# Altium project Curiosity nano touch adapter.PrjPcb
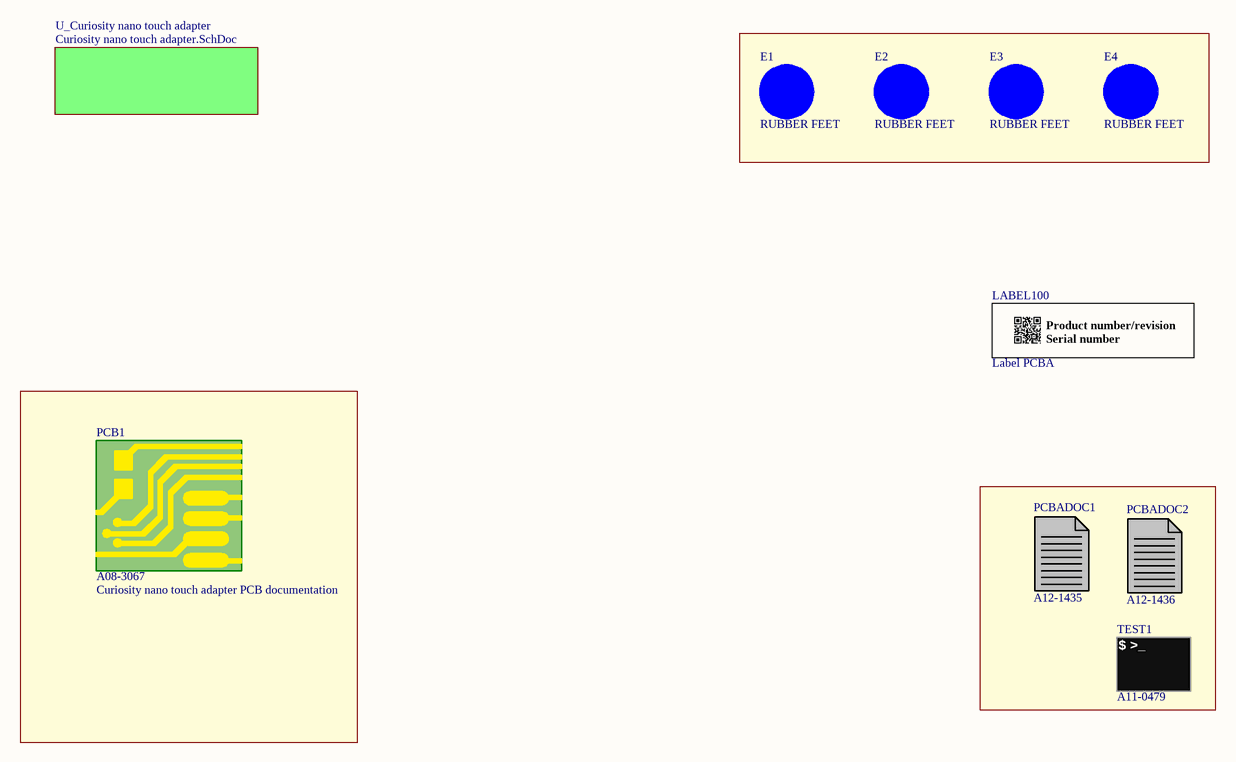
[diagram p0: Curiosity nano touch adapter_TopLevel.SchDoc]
ProjectTitle: Curiosity nano touch adapter Kit; ProjectRevisionSCH: 1; ProjectRevisionFAB: 1; ProjectRevisionASSY: 1; ProjectRevisionART: 1; ProjectPartNumber: **; ProjectEngineer: Sivaram.SL; ProjectDrawnBy: Sivaram.SL; ProjectBoardNumber: **; PCBNumber_TLM: A12-1436; PCBANumber_TLM: A09-3346
2 sheets, 27 parts. Net scope: global (net labels, ports and power ports of the same name join across sheets).
Board file: Curiosity nano touch adapter.PcbDoc
Sheets:
  Curiosity nano touch adapter_TopLevel.SchDoc
    U_Curiosity nano touch adapter = Curiosity nano touch adapter.SchDoc

## Sheet Curiosity nano touch adapter_TopLevel.SchDoc: Top Level
size A3; Organization: ATMEL Norway; Address1: Vestre Rosten 79; Address2: N-7075 TILLER; Address3: NORWAY; DocumentNumber: 1; Revision: 3; SheetNumber: 1; SheetTotal: 2; PageSetup: Record=PageOptions¦CenterHorizontal=True¦CenterVertical=True¦PrintScale=1.01¦XCorrection=1.00¦YCorrection=1.00¦PrintKind=1¦BorderSize=5000000¦LeftOffset=0¦BottomOffset=0¦Orientation=2¦PaperLength=1000¦PaperWidth=1000¦Scale=100¦PaperSource=7¦PrintQuality=-4¦MediaType=1¦DitherType=10¦PaperKind=Letter¦PrintScaleMode=1

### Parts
?  (no value)  (graphical)
E1  RUBBER FEET  [AP8-00192]
E2  RUBBER FEET  [AP8-00192]
E3  RUBBER FEET  [AP8-00192]
E4  RUBBER FEET  [AP8-00192]
LABEL100  value Label PCBA  [AP8-00317]
PCB1  value Curiosity nano touch adapter PCB documentation  AN: A08-3067  (hidden comment: PCB)  (mechanical)
PCBADOC1  AN: A12-1435  (hidden comment: PCBADOC)  (mechanical)
PCBADOC2  AN: A12-1436  (hidden comment: PCBADOC)  (mechanical)
TEST1  AN: A11-0479  (hidden comment: TEST)  (mechanical)

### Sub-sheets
U_Curiosity nano touch adapter = Curiosity nano touch adapter.SchDoc: no entries

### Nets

Not connected (* = marked no-connect by the designer): E1 1(FIDUCIAL); E2 1(FIDUCIAL); E3 1(FIDUCIAL); E4 1(FIDUCIAL)

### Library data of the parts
? = Title Block A3
E1-E4 = A08-0053: 2.8mm adhesive feet,diam 8.0mm; PartGroup: Mechanical devices,Mounting accessories; Manufacturer: 3M; Value: SJ-5076; ComponentStatus: 'Active (verified)'
LABEL100 = A09-0611: PCBA identification label PP Top White Gloss; PartGroup: Mechanical devices,Packaging materials,Printed Labels; Manufacturer: ACT Logimark AS; MPN: 505462
PCB1 = A08-3067: Curiosity nano touch adapter PCB documentation; PartGroup: Mechanical devices,Printed circuit boards; ComponentStatus: 'Active (verified)'
PCBADOC1 = A12-1435: Curiosity nano touch adapter test Documentation; PartGroup: Documentation,Procedures,Test Instructions; ComponentStatus: 'Active (verified)'
PCBADOC2 = A12-1436: Curiosity nano touch adapter PCBA Documentation; PartGroup: Documentation,PCBA Documents,Atmel; ComponentStatus: 'Active (verified)'
TEST1 = A11-0479: Fixture egg Test Curiosity nano touch adapter; PartGroup: Software,Test software,Starter Kit; Value: Curiosity nano touch adapter test software; ComponentStatus: 'Active (verified)'

## Sheet Curiosity nano touch adapter.SchDoc: Curiosity Nano Touch Board
size A3; Organization: Microchip; Address1: 2355 W Chandler Blvd; Address2: Chandler, AZ 85224; Address3: USA; DocumentNumber: 2; Revision: 3; SheetNumber: 2; SheetTotal: 2; PageSetup: Record=PageOptions¦CenterHorizontal=True¦CenterVertical=True¦PrintScale=1.01¦XCorrection=1.00¦YCorrection=1.00¦PrintKind=1¦BorderSize=5000000¦LeftOffset=0¦BottomOffset=0¦Orientation=2¦PaperLength=1000¦PaperWidth=1000¦Scale=100¦PaperSource=7¦PrintQuality=-4¦MediaType=1¦DitherType=10¦PaperKind=A3 (297 x 420 mm)¦PrintScaleMode=1; ProjectTitle: Curiosity Nano Touch Adapter; PCBRevision: 3
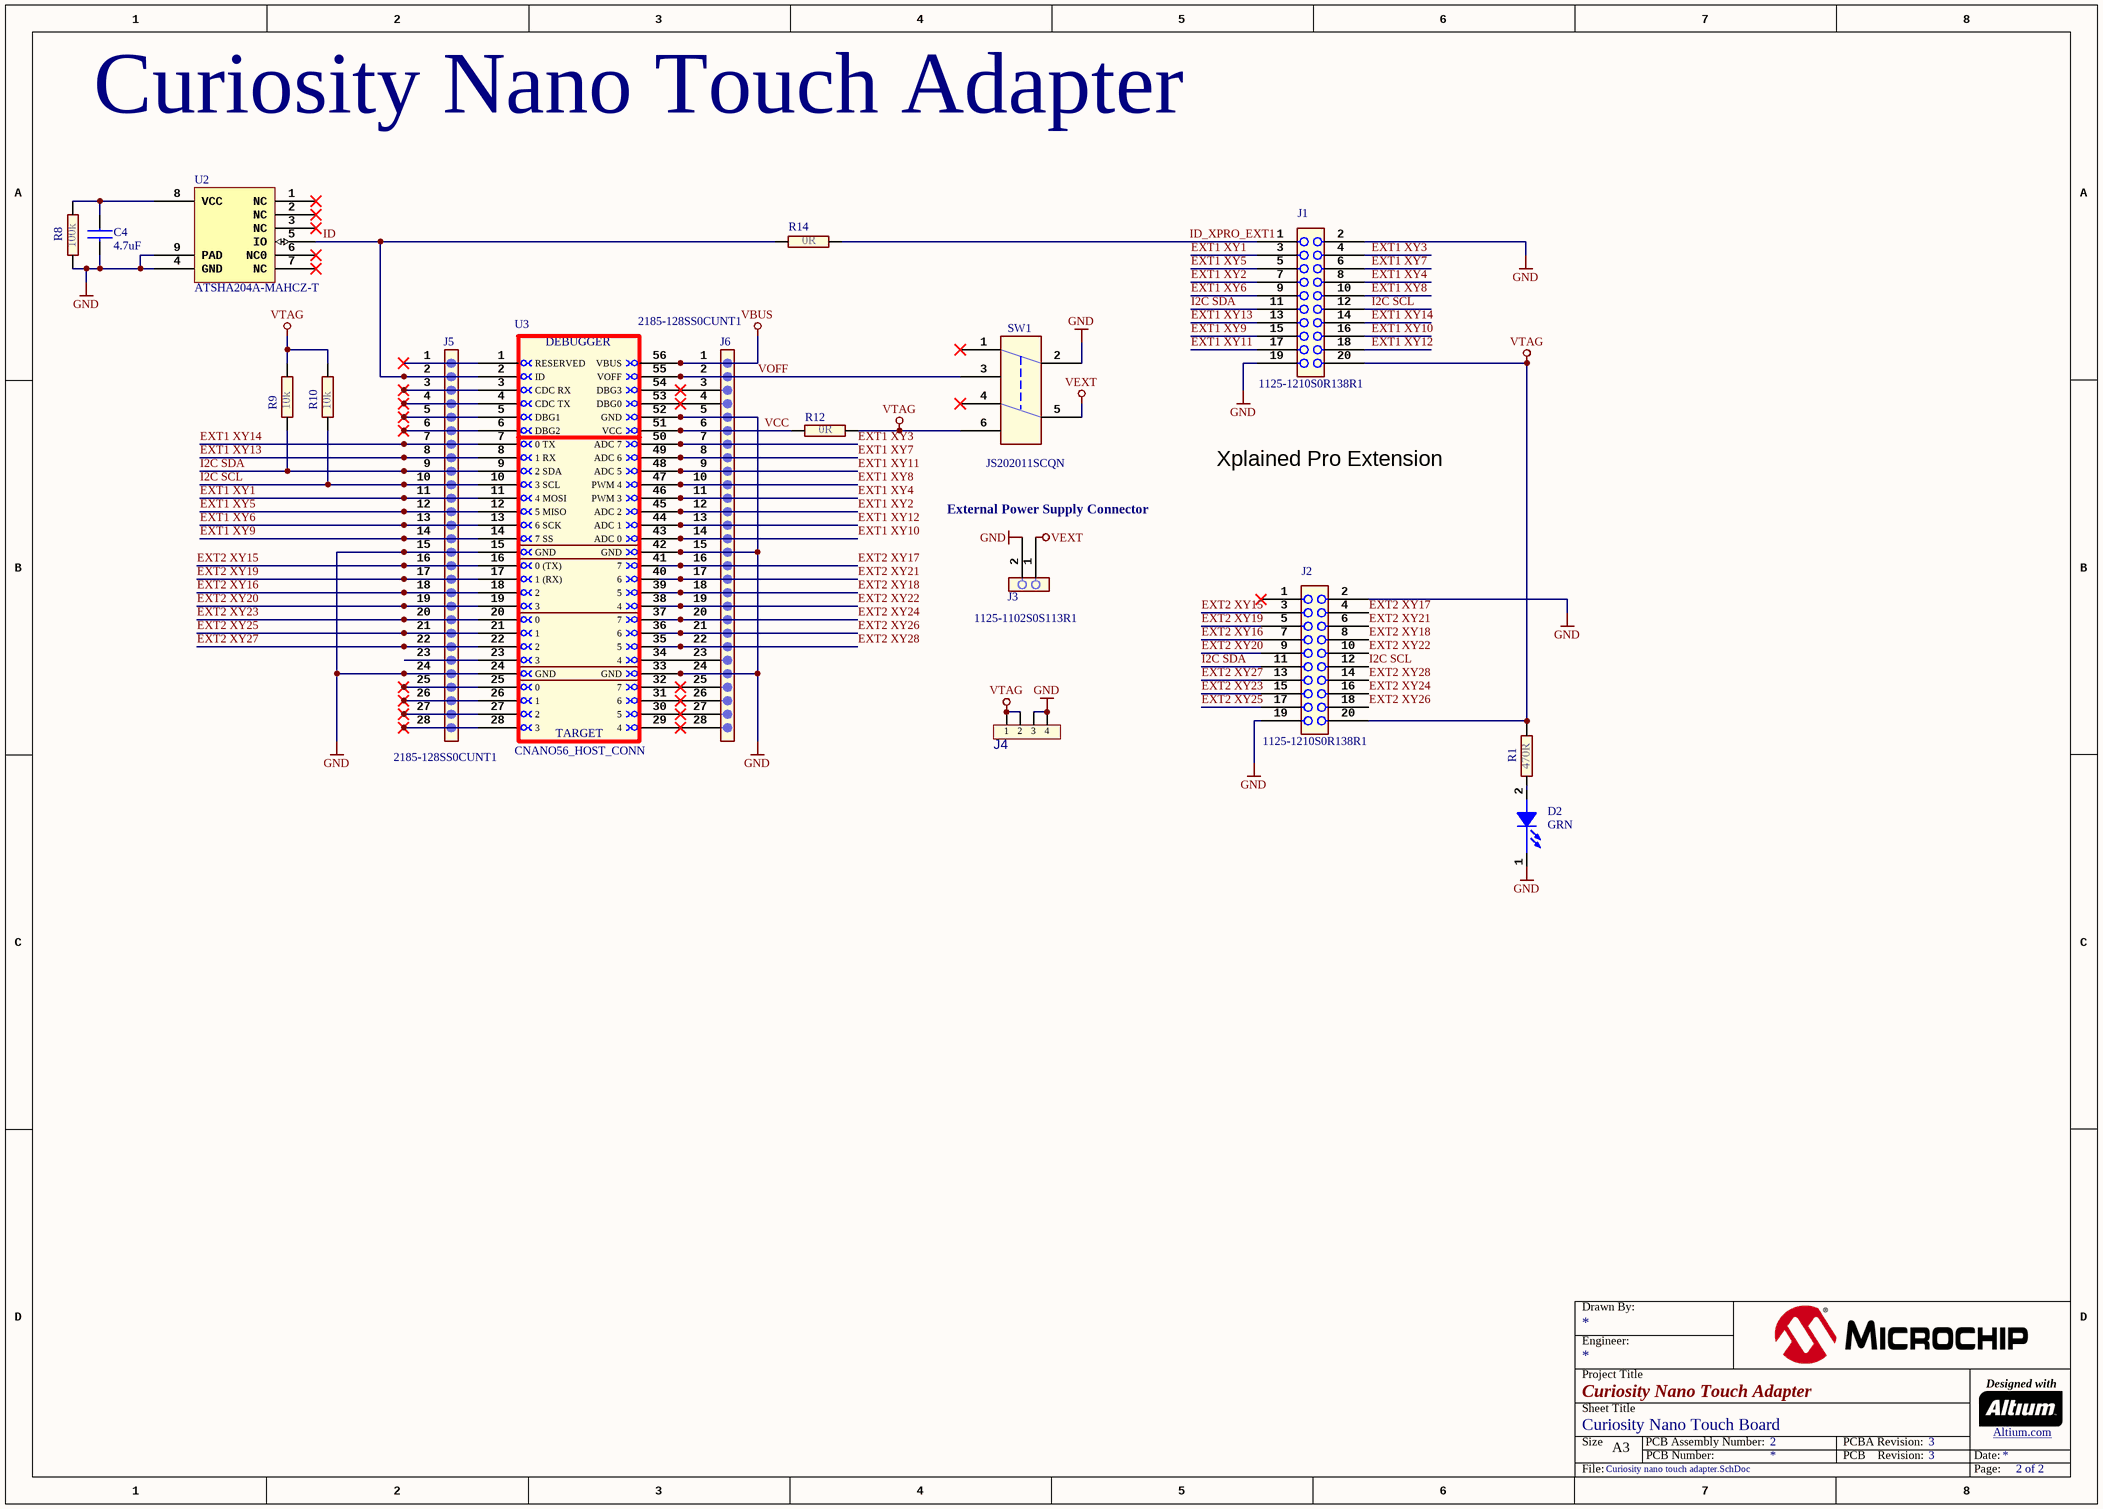
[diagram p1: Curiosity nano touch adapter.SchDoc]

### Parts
C4  value 4.7uF  [AP1-00069]  (hidden comment: Generic part, no manufacturer specified.)
D2  Color: GRN  [AP4-00017]  (hidden comment: Farnell no. 1652078)
J1  value 1125-1210S0R138R1  [AP8-01078]
J2  value 1125-1210S0R138R1  [AP8-01078]
J3  value 1125-1102S0S113R1  [AP8-01074]  (hidden comment: HEADER 1x2)
J4  Header 1x4  [HDR_M_2.54_1x4]  (value not drawn)
J5  value 2185-128SS0CUNT1  [AP8-01174]  (hidden comment: Not suitable for pick-and-place (missing tab))
J6  value 2185-128SS0CUNT1  [AP8-01174]  (hidden comment: Not suitable for pick-and-place (missing tab))
R1  value 470R  [AP2-00000]
R8  value 100k  [AP2-00000]
R9  value 10k  [AP2-00000]
R10  value 10k  [AP2-00000]
R12  value 0R  [AP2-00000]
R14  value 0R  [AP2-00000]
SW1  value JS202011SCQN  [AP8-00684]
U2  MPN: ATSHA204A-MAHCZ-T  [AP6-00409]
U3  value CNANO56_HOST_CONN  [AP8-01154]  (no BOM)

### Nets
GND: C4.2 D2.1(CATHODE) J1.2 J1.19 J2.2 J2.19 J3.2 J4.3 J4.4 J5.15 J5.24 J6.5 J6.15 J6.24 R8.2 SW1.2(COMMON2) U2.4(GND) U2.9(PAD) U3.15(GND) U3.24(GND) U3.33(GND) U3.42(GND) U3.52(GND)
VBUS: J6.1 U3.56(VBUS)
VEXT: J3.1 SW1.5(COMMON1)
VTAG: J1.20 J2.20 J4.1 J4.2 R1.1 R9.1 R10.1 R12.2 SW1.6(NC1)
EXT1 XY1: J1.3 J5.11 U3.11(4_MOSI)
EXT1 XY2: J1.7 J6.12 U3.45(ADC_2)
EXT1 XY3: J1.4 J6.7 U3.50(ADC_7)
EXT1 XY4: J1.8 J6.11 U3.46(PWM_3)
EXT1 XY5: J1.5 J5.12 U3.12(5_MISO)
EXT1 XY6: J1.9 J5.13 U3.13(6_SCK)
EXT1 XY7: J1.6 J6.8 U3.49(ADC_6)
EXT1 XY8: J1.10 J6.10 U3.47(PWM_4)
EXT1 XY9: J1.15 J5.14 U3.14(7_SS)
EXT1 XY10: J1.16 J6.14 U3.43(ADC_0)
EXT1 XY11: J1.17 J6.9 U3.48(ADC_5)
EXT1 XY12: J1.18 J6.13 U3.44(ADC_1)
EXT1 XY13: J1.13 J5.8 U3.8(1_RX)
EXT1 XY14: J1.14 J5.7 U3.7(0_TX)
EXT2 XY15: J2.3 J5.16 U3.16(0_(TX))
EXT2 XY16: J2.7 J5.18 U3.18(2)
EXT2 XY17: J2.4 J6.16 U3.41(7)
EXT2 XY18: J2.8 J6.18 U3.39(5)
EXT2 XY19: J2.5 J5.17 U3.17(1_(RX))
EXT2 XY20: J2.9 J5.19 U3.19(3)
EXT2 XY21: J2.6 J6.17 U3.40(6)
EXT2 XY22: J2.10 J6.19 U3.38(4)
EXT2 XY23: J2.15 J5.20 U3.20(0)
EXT2 XY24: J2.16 J6.20 U3.37(7)
EXT2 XY25: J2.17 J5.21 U3.21(1)
EXT2 XY26: J2.18 J6.21 U3.36(6)
EXT2 XY27: J2.13 J5.22 U3.22(2)
EXT2 XY28: J2.14 J6.22 U3.35(5)
I2C SCL: J1.12 J2.12 J5.10 R10.2 U3.10(3_SCL)
I2C SDA: J1.11 J2.11 J5.9 R9.2 U3.9(2_SDA)
ID: J5.2 R14.1 U2.5(IO) U3.2(ID)
ID_XPRO_EXT1: J1.1 R14.2
VCC: J6.6 R12.1 U3.51(VCC)
VOFF: J6.2 SW1.3(NC2) U3.55(VOFF)
NetC4_1: C4.1 R8.1 U2.8(VCC)
NetD2_2: D2.2(ANODE) R1.2
NetJ5_1: J5.1 U3.1(RESERVED)
NetJ5_3: J5.3 U3.3(CDC_RX)
NetJ5_4: J5.4 U3.4(CDC_TX)
NetJ5_5: J5.5 U3.5(DBG1)
NetJ5_6: J5.6 U3.6(DBG2)
NetJ5_23: J5.23 U3.23(3)
NetJ5_25: J5.25 U3.25(0)
NetJ5_26: J5.26 U3.26(1)
NetJ5_27: J5.27 U3.27(2)
NetJ5_28: J5.28 U3.28(3)
NetJ6_3: J6.3 U3.54(DBG3)
NetJ6_4: J6.4 U3.53(DBG0)
NetJ6_23: J6.23 U3.34(4)
NetJ6_25: J6.25 U3.32(7)
NetJ6_26: J6.26 U3.31(6)
NetJ6_27: J6.27 U3.30(5)
NetJ6_28: J6.28 U3.29(4)

Not connected (* = marked no-connect by the designer): J2 1*; SW1 1(NO2)* 4(NO1)*; U2 1(NC)* 2(NC)* 3(NC)* 6(NC0)* 7(NC)*

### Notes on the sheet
- Curiosity Nano Touch Adapter
- External Power Supply Connector
- Xplained Pro Extension
- Drawn By:
- Project Title
- Engineer:
- Designed with
- Sheet Title
- Size
- A3
- PCB Number:
- PCB Assembly Number:
- PCBA Revision:
- PCB    Revision:
- Date:
- Altium.com <http://go.altium.com/MicrochipLandingPage_Evaluation.html>
- File:
- Page:

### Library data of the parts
C4 = A01-0486: Ceramic capacitor, SMD 0805, X7R, 16V, 10%,; PartGroup: Capacitors,Ceramic,SMD 0805; Manufacturer: YAGEO CORP; MPN: CC0805KKX7R7BB475; TemperatureRange: -55 to +125 deg C; ComponentStatus: 'Active (verified)'
D2 = A10-0056: LED, Green, 570nm, SMD 0603; PartGroup: Opto,LEDs,SMD; Manufacturer: ROHM; Value: SML-310MTT86N; TemperatureRange: -30; ComponentStatus: 'Active (verified)'
J1 J2 = A08-2786: Pin header, 2x10, Right Angle, 2.54mm, THM, Pin In Paste; PartGroup: Mechanical devices,Connectors,Pin headers; Manufacturer: WCON HARDWARE ELECTRONICS CO., LTD; ComponentStatus: 'Active (verified)'
J3 = A08-2782: 1x2 pin header, 2.54mm pitch, Pin-in-Paste THM; PartGroup: Mechanical devices,Connectors,Pin headers; Manufacturer: WCON HARDWARE ELECTRONICS CO., LTD; TemperatureRange: -40Â°C to +105Â°C; ComponentStatus: 'Active (verified)'
J4 = CON0148: Manufacturer 1: Wurth Electronics Inc; Manufacturer Part Number 1: 61300411121; Description_: CON HDR-2.54 Male 1x4 Gold 5.84MH TH VERT; Dev Tools Status: Production; Populated: Yes
J5 J6 = A08-2989: 1x28 receptacle pin socket, 2.54mm pitch THM, BULK packaging; PartGroup: Mechanical devices,Connectors,Pin header receptacle; Manufacturer: WCON; TemperatureRange: -40Â°C to +105Â°C; ComponentStatus: 'Active (verified)'
R1 = A02-0204: Thick film resistor, SMD 0402, 1/16W, 1%; PartGroup: Resistors,SMD,0402 1%; Manufacturer: ASJ; MPN: CR10-4700-FK; ComponentStatus: 'Active (verified)'; TemperatureRange: -55 - +125 deg C
R8 = A02-0260: Thick film resistor, SMD 0402, 1/16W, 1%; PartGroup: Resistors,SMD,0402 1%; Manufacturer: ASJ; MPN: CR10-1003-FK; ComponentStatus: 'Active (verified)'; TemperatureRange: -55ï¿½ to +125ï¿½C
R9 R10 = A02-0236: Thick film resistor, SMD 0402, 1/16W, 1%; PartGroup: Resistors,SMD,0402 1%; Manufacturer: vishay; MPN: CRCW040210K0FKED; ComponentStatus: 'Active (verified)'; TemperatureRange: -55 - +125 deg C
R12 R14 = A02-0163: RES 0.0 OHM 1/16W 0402 SMD; PartGroup: Resistors,SMD,0402 1%; Manufacturer: (n/a); MPN: RMCF0402ZT0R00; Tolerance: 1 %; ComponentStatus: 'Active (verified)'; TemperatureRange: -55 - +125 deg C
SW1 = A08-1643: Slide Switch, C&K, 2 Pos 2 Pol, SMD; PartGroup: Mechanical devices,Switches,SMD; Manufacturer: C&K Components; Verfied by: shelgeland; ComponentStatus: 'Active (verified)'
U2 = A06-1276: ATSHA204A with 1-wire interface and UDFN8 package; PartGroup: Integrated Circuits,Special function,Encryption; Manufacturer: ATMEL; Value: ATSHA204A SWI UDFN8; ComponentStatus: 'Active (verified)'
U3 = A08-2940: 56-pin Header HOST (for CNANO solder mounting); PartGroup: Mechanical devices,Connectors,Pin headers; ComponentStatus: 'Active (verified)'

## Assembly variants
Default Assembly: not fitted J4 U3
